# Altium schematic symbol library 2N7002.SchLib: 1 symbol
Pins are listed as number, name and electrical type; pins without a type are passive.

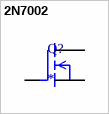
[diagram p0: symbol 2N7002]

## 2N7002
designator Q?
N-Channel 60V 200mA _Tc_ 350mW _Tc_ Surface Mount SOT-23-3; MP: 2N7002; MF: STMicroelectronics
footprint 2N7002
pins: 1 G, 2 S, 3 D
